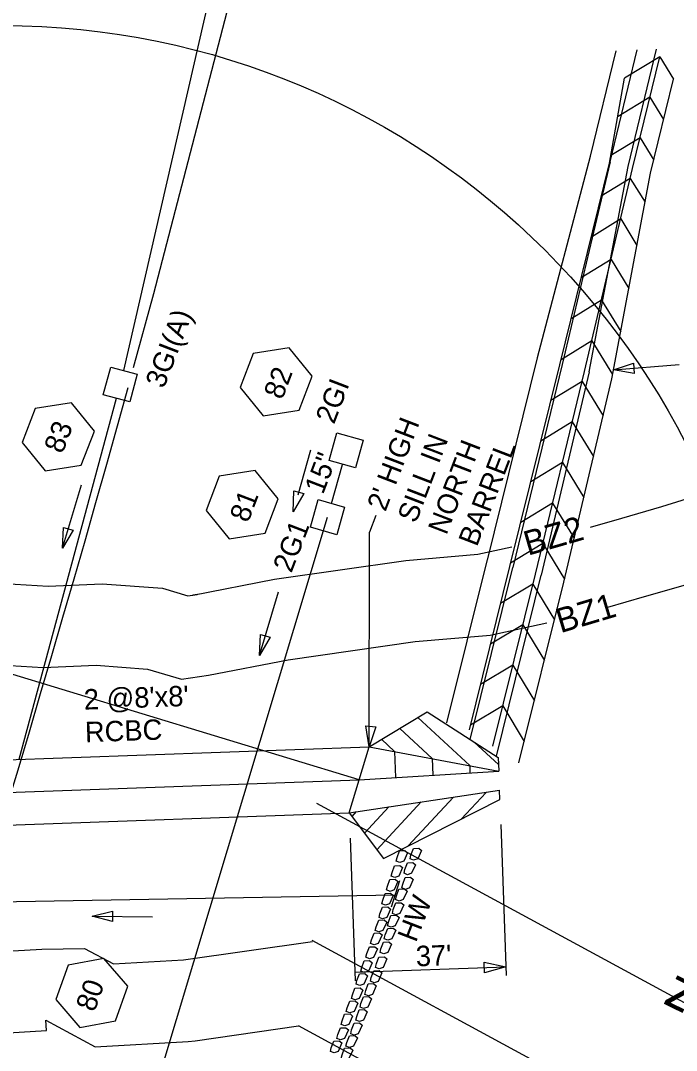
# Model space of a CAD drawing. Extents: x 2384780 to 2405432, y 547869 to 573706.
# Drawn here: x 2400242.9 to 2400403.5, y 562546.1 to 562798.4 of the extents above; entities that cross this region are included whole.
import ezdxf

# ---------------------------------------------------------------- set-up
doc = ezdxf.new("R2010")
doc.units = 0
for name, color, linetype in [('Old_Level_1', 7, 'Continuous'), ('Old_Level_10', 7, 'Continuous'), ('Old_Level_18', 7, 'Continuous'), ('Old_Level_19', 7, 'Continuous'), ('Old_Level_20', 7, 'Continuous'), ('Old_Level_23', 7, 'Continuous'), ('Old_Level_48', 7, 'Continuous'), ('Old_Level_5', 7, 'Continuous'), ('Old_Level_6', 7, 'Continuous'), ('Old_Level_63', 7, 'Continuous'), ('Old_Level_9', 7, 'Continuous'), ('Prop Buffer Zone 1', 7, 'Continuous'), ('Prop Buffer Zone 2', 7, 'Continuous'), ('Prop Drainage Box Number Symbol CELL', 7, 'Continuous')]:
    doc.layers.add(name, color=color, linetype=linetype)

msp = doc.modelspace()

# ---------------------------------------------------------------- linework, layer by layer
at = {"layer": 'Old_Level_1'}
for p, q in [((2400268.19, 562712.67), (2400363.16, 563127.62)), ((2400242.48, 562617.44), (2400266.36, 562705.89)), ((2400319.03, 562680.15), (2400321.71, 562689.69)), ((2400265.51, 562502.09), (2400318.08, 562676.77)), ((2400329.88, 562677.22), (2400328.3, 562673.1)), ((2400328.27, 562620.53), (2400328.3, 562673.1)), ((2400340.21, 562627.69), (2400352.89, 562615.9)), ((2400342.48, 562629.05), (2400359.89, 562617.92)), ((2400335.75, 562625.01), (2400343.68, 562617.63)), ((2400331.28, 562622.34), (2400334.48, 562619.36)), ((2400328.27, 562620.53), (2400360.01, 562614.55)), ((2400334.48, 562619.36), (2400334.71, 562612.99)), ((2400354.01, 562621.67), (2400359.95, 562616.15)), ((2400343.68, 562617.63), (2400343.83, 562613.55)), ((2400359.89, 562617.92), (2400360.01, 562614.55)), ((2400325.81, 562612.44), (2400360.01, 562614.55)), ((2400352.89, 562615.9), (2400352.95, 562614.12)), ((2400323.35, 562604.34), (2400360.18, 562609.84)), ((2400350.76, 562602.77), (2400356.88, 562609.34)), ((2400360.26, 562607.58), (2400360.18, 562609.84)), ((2400330.15, 562595.29), (2400341.02, 562606.98)), ((2400331.76, 562593.14), (2400360.26, 562607.58)), ((2400337.83, 562596.22), (2400348.95, 562608.16)), ((2400324.05, 562603.42), (2400325.16, 562604.61)), ((2400327.1, 562599.35), (2400333.09, 562605.8)), ((2400360.48, 562601.5), (2400361.81, 562564.49)), ((2400323.58, 562598.11), (2400324.83, 562563.16)), ((2400133.91, 562580.63), (2400334.53, 562584.25)), ((2400324.76, 562565.26), (2400361.73, 562566.59))]:
    msp.add_line(p, q, dxfattribs=at)
for points in [[(2400313.9, 562674.29), (2400315.8, 562681.06), (2400322.25, 562679.24), (2400320.35, 562672.48)], [(2400329.92, 562625.41), (2400328.27, 562620.53), (2400327.43, 562625.62)]]:
    msp.add_lwpolyline(points, close=True, dxfattribs=at)
at = {"layer": 'Old_Level_10'}
for p, q in [((2400328.27, 562620.53), (2400342.48, 562629.05)), ((2400158.94, 562614.44), (2400328.27, 562620.53)), ((2400323.35, 562604.34), (2400328.27, 562620.53)), ((2400156.49, 562606.35), (2400325.81, 562612.44)), ((2400154.03, 562598.25), (2400323.35, 562604.34)), ((2400323.35, 562604.34), (2400331.76, 562593.14))]:
    msp.add_line(p, q, dxfattribs=at)
at = {"layer": 'Old_Level_18'}
for p, q in [((2400399.45, 562789.6), (2400390.79, 562784.33)), ((2400399.45, 562789.6), (2400402.79, 562784.11)), ((2400397.03, 562779.67), (2400389.22, 562774.91)), ((2400397.03, 562779.67), (2400400.37, 562774.18)), ((2400394.61, 562769.73), (2400387.49, 562765.39)), ((2400394.61, 562769.73), (2400397.96, 562764.24)), ((2400392.21, 562759.79), (2400385.1, 562755.4)), ((2400392.21, 562759.79), (2400395.84, 562753.92)), ((2400389.86, 562749.84), (2400382.68, 562745.41)), ((2400389.86, 562749.84), (2400393.85, 562743.37)), ((2400387.5, 562739.89), (2400380.2, 562735.38)), ((2400387.5, 562739.89), (2400391.86, 562732.82)), ((2400385.14, 562729.94), (2400377.93, 562725.49)), ((2400385.14, 562729.94), (2400389.87, 562722.27)), ((2400382.78, 562719.98), (2400375.26, 562715.34)), ((2400382.78, 562719.98), (2400387.89, 562711.71)), ((2400380.41, 562710.04), (2400372.78, 562705.38)), ((2400380.41, 562710.04), (2400385.55, 562701.62)), ((2400378, 562700.1), (2400370.31, 562695.41)), ((2400378, 562700.1), (2400383.18, 562691.61)), ((2400375.59, 562690.16), (2400367.84, 562685.43)), ((2400375.59, 562690.16), (2400380.81, 562681.6)), ((2400373.19, 562680.22), (2400365.38, 562675.46)), ((2400373.19, 562680.22), (2400378.45, 562671.59)), ((2400370.78, 562670.28), (2400362.91, 562665.49)), ((2400370.78, 562670.28), (2400376.08, 562661.58)), ((2400368.35, 562660.35), (2400360.46, 562655.58)), ((2400368.35, 562660.35), (2400373.63, 562651.61)), ((2400365.9, 562650.42), (2400358.01, 562645.65)), ((2400365.9, 562650.42), (2400371.17, 562641.69)), ((2400363.45, 562640.49), (2400355.55, 562635.73)), ((2400363.45, 562640.49), (2400368.72, 562631.76)), ((2400360.99, 562630.56), (2400353.1, 562625.8)), ((2400360.99, 562630.56), (2400366.26, 562621.83))]:
    msp.add_line(p, q, dxfattribs=at)
for points in [[(2400358.54, 562620.63), (2400368.96, 562662.8), (2400381.01, 562712.48), (2400392.78, 562762.2), (2400399.45, 562789.6)], [(2400352.82, 562624.69), (2400362.72, 562664.71), (2400374.94, 562714.11), (2400387.16, 562763.53), (2400390.79, 562784.33)], [(2400364.95, 562616.54), (2400375.91, 562660.85), (2400387.69, 562710.68), (2400397.18, 562761.06), (2400402.79, 562784.11)]]:
    msp.add_lwpolyline(points, dxfattribs=at)
at = {"layer": 'Old_Level_19'}
msp.add_lwpolyline([(2400390.56, 563281.58), (2400376.7, 563195.08), (2400367.07, 563139.3), (2400354.77, 563073.27), (2400343.48, 563016.73), (2400332.03, 562962.8), (2400319.46, 562906.83), (2400301.79, 562832.99), (2400275.44, 562731.47), (2400270.41, 562713.36)], dxfattribs=at)
msp.add_arc((2395691.88, 563975.57), 4749.45, 337.00198, 344.52777, dxfattribs=at)
at = {"layer": 'Old_Level_20'}
for points in [[(2400334.87, 562592.46), (2400335.08, 562593.38), (2400335.7, 562595.01), (2400337.03, 562595.08), (2400337.68, 562594.54), (2400336.74, 562592.46), (2400335.74, 562592.12), (2400334.87, 562592.46)], [(2400338.26, 562593.04), (2400338.48, 562593.96), (2400339.1, 562595.59), (2400340.42, 562595.66), (2400341.07, 562595.12), (2400340.14, 562593.04), (2400339.14, 562592.7), (2400338.26, 562593.04)], [(2400336.79, 562589.5), (2400337.01, 562590.42), (2400337.63, 562592.05), (2400338.95, 562592.12), (2400339.6, 562591.58), (2400338.66, 562589.5), (2400337.67, 562589.16), (2400336.79, 562589.5)], [(2400333.63, 562588.82), (2400333.85, 562589.74), (2400334.47, 562591.37), (2400335.79, 562591.44), (2400336.44, 562590.9), (2400335.5, 562588.82), (2400334.51, 562588.48), (2400333.63, 562588.82)], [(2400332.49, 562585.42), (2400332.71, 562586.34), (2400333.33, 562587.97), (2400334.66, 562588.04), (2400335.31, 562587.5), (2400334.37, 562585.42), (2400333.37, 562585.08), (2400332.49, 562585.42)], [(2400336.24, 562585.91), (2400336.46, 562586.83), (2400337.08, 562588.46), (2400338.4, 562588.53), (2400339.05, 562587.99), (2400338.11, 562585.91), (2400337.12, 562585.57), (2400336.24, 562585.91)], [(2400331.36, 562582.02), (2400331.57, 562582.94), (2400332.2, 562584.57), (2400333.52, 562584.64), (2400334.17, 562584.1), (2400333.23, 562582.02), (2400332.23, 562581.68), (2400331.36, 562582.02)], [(2400334.72, 562583.05), (2400334.94, 562583.98), (2400335.56, 562585.6), (2400336.88, 562585.67), (2400337.53, 562585.14), (2400336.59, 562583.05), (2400335.6, 562582.72), (2400334.72, 562583.05)], [(2400333.93, 562579.68), (2400334.14, 562580.6), (2400334.77, 562582.23), (2400336.09, 562582.3), (2400336.74, 562581.76), (2400335.8, 562579.68), (2400334.8, 562579.34), (2400333.93, 562579.68)], [(2400330.68, 562578.65), (2400330.89, 562579.57), (2400331.52, 562581.2), (2400332.84, 562581.27), (2400333.49, 562580.73), (2400332.55, 562578.65), (2400331.55, 562578.31), (2400330.68, 562578.65)], [(2400332.77, 562576.62), (2400332.98, 562577.54), (2400333.6, 562579.17), (2400334.93, 562579.24), (2400335.58, 562578.7), (2400334.64, 562576.62), (2400333.64, 562576.28), (2400332.77, 562576.62)], [(2400329.75, 562575.49), (2400329.97, 562576.41), (2400330.59, 562578.04), (2400331.91, 562578.11), (2400332.56, 562577.57), (2400331.63, 562575.49), (2400330.63, 562575.15), (2400329.75, 562575.49)], [(2400328.6, 562572.32), (2400328.81, 562573.24), (2400329.44, 562574.87), (2400330.76, 562574.94), (2400331.41, 562574.4), (2400330.47, 562572.32), (2400329.48, 562571.98), (2400328.6, 562572.32)], [(2400331.95, 562573.47), (2400332.17, 562574.39), (2400332.79, 562576.02), (2400334.12, 562576.09), (2400334.77, 562575.55), (2400333.83, 562573.47), (2400332.83, 562573.13), (2400331.95, 562573.47)], [(2400327.46, 562568.92), (2400327.68, 562569.84), (2400328.3, 562571.46), (2400329.62, 562571.53), (2400330.27, 562571), (2400329.34, 562568.91), (2400328.34, 562568.58), (2400327.46, 562568.92)], [(2400330.93, 562570.07), (2400331.15, 562571), (2400331.77, 562572.62), (2400333.09, 562572.69), (2400333.74, 562572.16), (2400332.81, 562570.07), (2400331.81, 562569.74), (2400330.93, 562570.07)], [(2400329.81, 562566.45), (2400330.03, 562567.37), (2400330.65, 562568.99), (2400331.97, 562569.06), (2400332.62, 562568.53), (2400331.69, 562566.44), (2400330.69, 562566.11), (2400329.81, 562566.45)], [(2400326.21, 562565.51), (2400326.43, 562566.43), (2400327.05, 562568.05), (2400328.37, 562568.13), (2400329.02, 562567.59), (2400328.09, 562565.5), (2400327.09, 562565.17), (2400326.21, 562565.51)], [(2400325.06, 562562.33), (2400325.27, 562563.26), (2400325.9, 562564.88), (2400327.22, 562564.95), (2400327.87, 562564.41), (2400326.93, 562562.33), (2400325.94, 562562), (2400325.06, 562562.33)], [(2400328.56, 562563.04), (2400328.78, 562563.96), (2400329.4, 562565.58), (2400330.72, 562565.65), (2400331.37, 562565.12), (2400330.43, 562563.03), (2400329.44, 562562.7), (2400328.56, 562563.04)], [(2400323.93, 562558.82), (2400324.15, 562559.74), (2400324.77, 562561.37), (2400326.09, 562561.44), (2400326.74, 562560.9), (2400325.8, 562558.82), (2400324.81, 562558.48), (2400323.93, 562558.82)], [(2400327.18, 562559.85), (2400327.4, 562560.77), (2400328.02, 562562.4), (2400329.34, 562562.47), (2400329.99, 562561.93), (2400329.05, 562559.84), (2400328.06, 562559.51), (2400327.18, 562559.85)], [(2400326.03, 562556.67), (2400326.24, 562557.6), (2400326.87, 562559.22), (2400328.19, 562559.29), (2400328.84, 562558.75), (2400327.9, 562556.67), (2400326.9, 562556.34), (2400326.03, 562556.67)], [(2400322.66, 562555.64), (2400322.88, 562556.56), (2400323.5, 562558.18), (2400324.83, 562558.26), (2400325.48, 562557.72), (2400324.54, 562555.63), (2400323.54, 562555.3), (2400322.66, 562555.64)], [(2400321.4, 562552.45), (2400321.61, 562553.38), (2400322.24, 562555), (2400323.56, 562555.07), (2400324.21, 562554.53), (2400323.27, 562552.45), (2400322.27, 562552.12), (2400321.4, 562552.45)], [(2400324.99, 562553.51), (2400325.2, 562554.43), (2400325.83, 562556.06), (2400327.15, 562556.13), (2400327.8, 562555.59), (2400326.86, 562553.51), (2400325.87, 562553.17), (2400324.99, 562553.51)], [(2400320.37, 562549.06), (2400320.59, 562549.99), (2400321.21, 562551.61), (2400322.54, 562551.68), (2400323.19, 562551.14), (2400322.25, 562549.06), (2400321.25, 562548.72), (2400320.37, 562549.06)], [(2400323.73, 562550.21), (2400323.95, 562551.14), (2400324.57, 562552.76), (2400325.89, 562552.83), (2400326.54, 562552.29), (2400325.6, 562550.21), (2400324.61, 562549.88), (2400323.73, 562550.21)], [(2400322.57, 562547.15), (2400322.78, 562548.08), (2400323.41, 562549.7), (2400324.73, 562549.77), (2400325.38, 562549.23), (2400324.44, 562547.15), (2400323.45, 562546.82), (2400322.57, 562547.15)], [(2400318.76, 562545.86), (2400318.98, 562546.78), (2400319.6, 562548.4), (2400320.93, 562548.47), (2400321.58, 562547.94), (2400320.64, 562545.85), (2400319.64, 562545.52), (2400318.76, 562545.86)], [(2400321.41, 562544.09), (2400321.62, 562545.02), (2400322.25, 562546.64), (2400323.57, 562546.71), (2400324.22, 562546.17), (2400323.28, 562544.09), (2400322.29, 562543.76), (2400321.41, 562544.09)]]:
    msp.add_lwpolyline(points, dxfattribs=at)
at = {"layer": 'Old_Level_23'}
msp.add_lwpolyline([(2400356.41, 562567.72), (2400361.73, 562566.59), (2400356.51, 562565.08)], close=True, dxfattribs=at)
at = {"layer": 'Old_Level_48'}
for p, q in [((2400382.43, 562765.19), (2400388.73, 562791.06)), ((2400387.27, 562763.87), (2400393.94, 562791.28)), ((2400391.67, 562762.73), (2400398.66, 562791.47)), ((2400382.41, 562765.12), (2400369.43, 562715.78)), ((2400387.27, 562763.87), (2400375.49, 562714.15)), ((2400382.18, 562712.35), (2400391.67, 562762.73)), ((2400369.43, 562715.78), (2400357.17, 562666.24)), ((2400375.49, 562714.15), (2400363.45, 562664.47)), ((2400382.18, 562712.35), (2400370.4, 562662.52)), ((2400347.31, 562626.36), (2400357.21, 562666.39)), ((2400353.03, 562622.31), (2400363.45, 562664.47)), ((2400359.44, 562618.21), (2400370.4, 562662.52))]:
    msp.add_line(p, q, dxfattribs=at)
at = {"layer": 'Old_Level_5'}
for p, q in [((2400388.1, 562712.84), (2400404.23, 562714.17)), ((2400313.88, 562693.19), (2400310.82, 562682.13)), ((2400253.11, 562669.14), (2400257.75, 562684.7)), ((2400301.38, 562642.89), (2400306.03, 562658.46)), ((2400335.65, 562587.63), (2400333.65, 562581.24)), ((2400260.37, 562579.04), (2400275.22, 562578.86))]:
    msp.add_line(p, q, dxfattribs=at)
for points in [[(2400393.18, 562712), (2400388.1, 562712.84), (2400392.98, 562714.49)], [(2400312.23, 562682.54), (2400309.6, 562678.11), (2400309.84, 562683.26)], [(2400255.74, 562673.57), (2400253.11, 562669.14), (2400253.34, 562674.28)], [(2400304.01, 562647.33), (2400301.38, 562642.89), (2400301.62, 562648.04)], [(2400265.36, 562577.73), (2400260.37, 562579.04), (2400265.39, 562580.23)]]:
    msp.add_lwpolyline(points, close=True, dxfattribs=at)
at = {"layer": 'Old_Level_6'}
msp.add_line((2400540.07, 562484.71), (2400315.42, 562606.6), dxfattribs=at)
at = {"layer": 'Old_Level_63'}
msp.add_line((2400325.81, 562612.44), (2400111.87, 562677.35), dxfattribs=at)
msp.add_circle((2400238.44, 562609.29), 187.94, dxfattribs=at)
at = {"layer": 'Old_Level_9'}
for points in [[(2400263.13, 562706.76), (2400264.96, 562713.54), (2400271.43, 562711.8), (2400269.59, 562705.01)], [(2400318.48, 562690.66), (2400320.35, 562697.43), (2400326.81, 562695.65), (2400324.94, 562688.88)]]:
    msp.add_lwpolyline(points, close=True, dxfattribs=at)
at = {"layer": 'Prop Buffer Zone 1'}
for p, q in [((2400248.39, 562639.91), (2400261.38, 562640.51)), ((2400387.85, 562533.17), (2400314.31, 562573.07)), ((2400248.09, 562570.94), (2400258.51, 562571.1))]:
    msp.add_line(p, q, dxfattribs=at)
for points in [[(2400386.73, 562654.74), (2400395.7, 562657.31), (2400405.73, 562660.2), (2400420.48, 562664.83), (2400438.08, 562669.56), (2400447.1, 562672.23)], [(2400357.91, 562647.86), (2400371.81, 562650.89)], [(2400288.93, 562638.02), (2400308.38, 562641.81), (2400339.54, 562646.27), (2400357, 562647.78), (2400357.91, 562647.86)], [(2400216.02, 562641.88), (2400248.39, 562639.91)], [(2400261.38, 562640.51), (2400273.95, 562639.56), (2400282.29, 562637.07), (2400288.93, 562638.02)], [(2400282.77, 562568.27), (2400314.35, 562572.83)], [(2400217.96, 562570.99), (2400229.47, 562569.85), (2400248.09, 562570.94)], [(2400258.51, 562571.1), (2400265.61, 562567.3), (2400282.77, 562568.27)]]:
    msp.add_lwpolyline(points, dxfattribs=at)
at = {"layer": 'Prop Buffer Zone 2'}
for p, q in [((2400249.6, 562659.88), (2400262.89, 562660.46)), ((2400286.1, 562657.82), (2400285.1, 562657.65)), ((2400249.25, 562550.97), (2400249.06, 562553.48)), ((2400376.29, 562516.69), (2400310.96, 562552.14)), ((2400283.9, 562548.3), (2400285.63, 562548.48))]:
    msp.add_line(p, q, dxfattribs=at)
for points in [[(2400382.45, 562674.32), (2400390.18, 562676.53), (2400399.98, 562679.35), (2400414.89, 562684.03), (2400432.64, 562688.81), (2400441.42, 562691.41)], [(2400285.1, 562657.65), (2400305.05, 562661.54), (2400337.26, 562666.15), (2400354.9, 562667.68)], [(2400354.91, 562667.68), (2400363.22, 562669.49)], [(2400217.23, 562661.84), (2400249.6, 562659.88)], [(2400262.89, 562660.46), (2400277.6, 562659.34), (2400283.81, 562657.49), (2400286.1, 562657.82)], [(2400249.06, 562553.48), (2400261.12, 562547.01), (2400283.9, 562548.3)], [(2400285.63, 562548.48), (2400310.96, 562552.14)], [(2400217.45, 562550.94), (2400229.07, 562549.79), (2400249.25, 562550.97)]]:
    msp.add_lwpolyline(points, dxfattribs=at)
at = {"layer": 'Prop Drainage Box Number Symbol CELL'}
for points in [[(2400308.69, 562718.29), (2400299.85, 562716.89), (2400296.64, 562708.53), (2400302.27, 562701.58), (2400311.11, 562702.98), (2400314.32, 562711.33)], [(2400255.31, 562704.82), (2400246.47, 562703.42), (2400243.26, 562695.06), (2400248.89, 562688.11), (2400257.73, 562689.51), (2400260.94, 562697.86)], [(2400300.34, 562688.19), (2400291.5, 562686.79), (2400288.29, 562678.43), (2400293.92, 562671.48), (2400302.76, 562672.88), (2400305.97, 562681.23)], [(2400263.3, 562568.63), (2400254.51, 562566.99), (2400251.53, 562558.55), (2400257.34, 562551.75), (2400266.14, 562553.39), (2400269.12, 562561.83)]]:
    msp.add_lwpolyline(points, close=True, dxfattribs=at)

# ---------------------------------------------------------------- texts
at = {"layer": 'Old_Level_1'}
for s, rotation, p in [("2' HIGH", 68.9999, (2400332.24, 562677.94)), ('SILL IN', 68.9999, (2400339.71, 562675.08)), ('NORTH', 68.9999, (2400347.18, 562672.21)), ('BARREL', 68.9999, (2400354.64, 562669.34)), ('2G1', 68.9999, (2400309.2, 562662.93)), ("37'", 2.0599, (2400339.77, 562566.7))]:
    msp.add_text(s, height=5, rotation=rotation, dxfattribs=at).set_placement(p)
at = {"layer": 'Old_Level_10'}
for s, p in [("2 @8'x8' ", (2400258.44, 562629.6)), ('RCBC', (2400258.72, 562621.6))]:
    msp.add_text(s, height=5, rotation=2.0598, dxfattribs=at).set_placement(p)
at = {"layer": 'Old_Level_20'}
msp.add_text('15"', height=5, rotation=68.9999, dxfattribs=at).set_placement((2400316.94, 562682.15))
at = {"layer": 'Old_Level_5'}
for s, p in [('3GI(A)', (2400277.96, 562708.09)), ('2GI', (2400319.64, 562699.35)), ('HW', (2400339.71, 562572.38))]:
    msp.add_text(s, height=5, rotation=68.9999, dxfattribs=at).set_placement(p)
at = {"layer": 'Old_Level_6'}
msp.add_text('z', height=10, rotation=153.5382, dxfattribs=at).set_placement((2400409.12, 562561.81))
at = {"layer": 'Prop Buffer Zone 1'}
msp.add_text('BZ1', height=6, rotation=16.6683, dxfattribs=at).set_placement((2400375.11, 562648.32))
at = {"layer": 'Prop Buffer Zone 2'}
msp.add_text('BZ2', height=6, rotation=16.1086, dxfattribs=at).set_placement((2400367.14, 562667.3))
at = {"layer": 'Prop Drainage Box Number Symbol CELL'}
for s, rotation, p in [('82', 68.9999, (2400306.94, 562705.36)), ('83', 68.9999, (2400253.11, 562692.12)), ('81', 68.9999, (2400298.59, 562675.22)), ('80', 70.3561, (2400260.97, 562555.33))]:
    msp.add_text(s, height=5, rotation=rotation, dxfattribs=at).set_placement(p)

doc.saveas('drawing.dxf')
